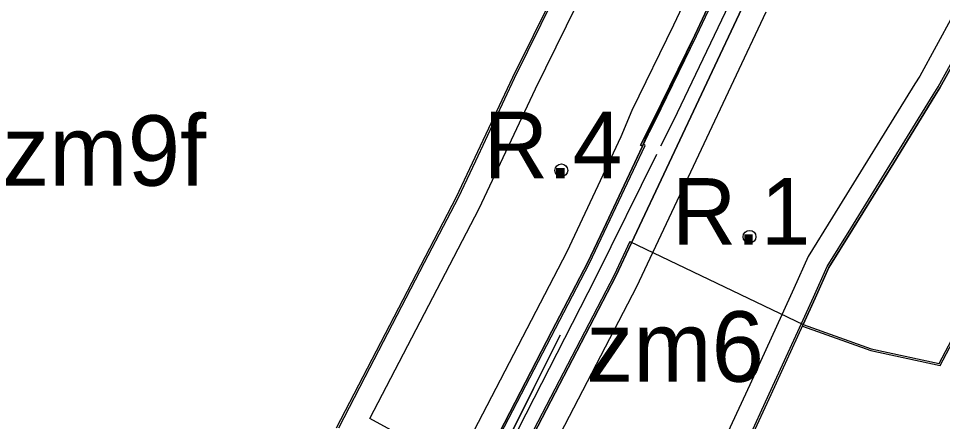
# Model space of a CAD drawing. Extents: x -555070 to -553076, y -1186731 to -1182766.
# Drawn here: x -554895.6 to -554659.4, y -1185299 to -1185196 of the extents above; entities that cross this region are included whole.
import ezdxf

# ---------------------------------------------------------------- set-up
doc = ezdxf.new("R2010")
doc.units = 0
for name, color, linetype in [('HRANICE_ZMENY_DO_KOO', 7, 'Continuous'), ('Level 10', 7, 'Continuous'), ('Level 13', 7, 'Continuous'), ('Level 4', 7, 'Continuous'), ('Level 46', 7, 'Continuous'), ('Level 52', 7, 'Continuous'), ('Level 6', 7, 'Continuous'), ('navrh_BV', 7, 'Continuous'), ('OBRYS_PLOCH', 7, 'Continuous'), ('rezerva_BV', 7, 'Continuous'), ('stav_BV', 7, 'Continuous'), ('stav_PU', 7, 'Continuous'), ('ZU_plocha_aktualizace', 7, 'Continuous')]:
    doc.layers.add(name, color=color, linetype=linetype)

msp = doc.modelspace()

# ---------------------------------------------------------------- linework, layer by layer
at = {"layer": 'HRANICE_ZMENY_DO_KOO'}
msp.add_line((-554739.32, -1185253.05), (-554694.99, -1185274.23), dxfattribs=at)
for points in [[(-554781.14, -1185319.16), (-554749.64, -1185258.53), (-554735.45, -1185228.43), (-554735.94, -1185228.17), (-554732.88, -1185222.18), (-554722.28, -1185200.47), (-554716.89, -1185189.03), (-554695.6, -1185133.26), (-554681.28, -1185085.12), (-554676.85, -1185071.58), (-554673.03, -1185055.54), (-554678.3, -1185053.24), (-554698.85, -1185044.53), (-554707.52, -1185040.87), (-554718.97, -1185084), (-554731.8, -1185124.46), (-554753.51, -1185179), (-554769.31, -1185211.12), (-554783.7, -1185241.67), (-554814.38, -1185300.72)], [(-554732.22, -1185344.93), (-554722.41, -1185327.9), (-554715.62, -1185316.12), (-554711.52, -1185309), (-554709.27, -1185304.1), (-554703.67, -1185291.93), (-554695.45, -1185274.02), (-554692.41, -1185267.29), (-554688.86, -1185259.43), (-554682.86, -1185249.71), (-554661.74, -1185215.55), (-554660.47, -1185213.5), (-554651.98, -1185198.08), (-554642.32, -1185180.53), (-554631.22, -1185160.38)], [(-554695.16, -1185274.7), (-554677.73, -1185280.92), (-554659.99, -1185284.76), (-554644.8, -1185256.02), (-554631.5, -1185230.24), (-554613.43, -1185198.97), (-554606.65, -1185185.13), (-554598.03, -1185166.4), (-554604.99, -1185165.25), (-554616.78, -1185160.64), (-554618.55, -1185165.81), (-554631.19, -1185160.33)], [(-554739.32, -1185253.05), (-554743.37, -1185261.64), (-554774.76, -1185322.08)]]:
    msp.add_lwpolyline(points, dxfattribs=at)
at = {"layer": 'Level 13'}
for p, q in [((-554753.06, -1185179.2), (-554768.86, -1185211.34)), ((-554722.73, -1185200.26), (-554717.35, -1185188.83)), ((-554709.98, -1185191.97), (-554738.91, -1185253.34)), ((-554651.54, -1185198.32), (-554660.04, -1185213.75)), ((-554660.04, -1185213.75), (-554651.54, -1185198.32)), ((-554733.33, -1185221.96), (-554722.73, -1185200.26)), ((-554768.86, -1185211.34), (-554778.8, -1185232.44)), ((-554660.04, -1185213.75), (-554661.31, -1185215.81)), ((-554661.31, -1185215.81), (-554671.87, -1185232.89)), ((-554736.6, -1185228.38), (-554733.33, -1185221.96)), ((-554746.09, -1185249.82), (-554736.11, -1185228.65)), ((-554736.11, -1185228.65), (-554736.6, -1185228.38)), ((-554778.8, -1185232.44), (-554783.25, -1185241.89)), ((-554671.87, -1185232.89), (-554682.43, -1185249.97)), ((-554682.43, -1185249.97), (-554671.87, -1185232.89)), ((-554783.25, -1185241.89), (-554791.87, -1185258.48)), ((-554750.09, -1185258.31), (-554746.09, -1185249.82)), ((-554682.43, -1185249.97), (-554688.42, -1185259.67)), ((-554688.42, -1185259.67), (-554682.43, -1185249.97)), ((-554738.91, -1185253.34), (-554742.92, -1185261.86)), ((-554759.23, -1185275.9), (-554750.09, -1185258.31)), ((-554791.87, -1185258.48), (-554807.06, -1185287.73)), ((-554688.42, -1185259.67), (-554691.95, -1185267.5)), ((-554691.95, -1185267.5), (-554688.42, -1185259.67)), ((-554742.92, -1185261.86), (-554774.32, -1185322.31)), ((-554691.95, -1185267.5), (-554694.99, -1185274.23)), ((-554694.99, -1185274.23), (-554691.95, -1185267.5)), ((-554703.22, -1185292.14), (-554694.99, -1185274.23)), ((-554694.99, -1185274.23), (-554677.59, -1185280.44)), ((-554774.2, -1185304.73), (-554759.23, -1185275.9)), ((-554677.59, -1185280.44), (-554660.25, -1185284.19)), ((-554807.06, -1185287.73), (-554813.83, -1185300.75)), ((-554708.82, -1185304.31), (-554703.22, -1185292.14))]:
    msp.add_line(p, q, dxfattribs=at)
for points in [[(-554660.25, -1185284.19), (-554645.24, -1185255.79), (-554631.94, -1185230), (-554613.87, -1185198.73), (-554607.1, -1185184.92), (-554598.76, -1185166.79), (-554605.12, -1185165.73)], [(-554671.87, -1185232.89), (-554661.31, -1185215.81), (-554660.04, -1185213.75)]]:
    msp.add_lwpolyline(points, dxfattribs=at)
at = {"layer": 'Level 4'}
for centre in [(-554756.84, -1185234.83), (-554708.72, -1185251.8)]:
    msp.add_circle(centre, 1.64, dxfattribs=at)
at = {"layer": 'Level 52'}
msp.add_lwpolyline([(-554651.54, -1185198.32), (-554660.04, -1185213.75), (-554661.31, -1185215.81), (-554671.87, -1185232.89), (-554682.43, -1185249.97), (-554688.42, -1185259.67), (-554691.95, -1185267.5), (-554694.99, -1185274.23)], dxfattribs=at)
at = {"layer": 'Level 6'}
for points in [[(-554731.38, -1185228.54), (-554728.11, -1185222.01), (-554710.22, -1185184.49), (-554693.2, -1185135.17), (-554681.62, -1185102.76), (-554672.29, -1185070.96), (-554668.89, -1185055.54)], [(-554732.53, -1185230.74), (-554748.07, -1185262.32), (-554769.87, -1185304.87)]]:
    msp.add_lwpolyline(points, dxfattribs=at)
at = {"layer": 'navrh_BV'}
for p, q in [((-554736.11, -1185228.65), (-554722.73, -1185200.26)), ((-554736.6, -1185228.38), (-554736.11, -1185228.65))]:
    msp.add_line(p, q, dxfattribs=at)
msp.add_lwpolyline([(-554722.73, -1185200.26), (-554733.33, -1185221.96), (-554736.6, -1185228.38)], dxfattribs=at)
at = {"layer": 'OBRYS_PLOCH'}
for p, q in [((-554717.35, -1185188.83), (-554722.73, -1185200.26)), ((-554717.35, -1185188.83), (-554722.73, -1185200.26)), ((-554738.91, -1185253.34), (-554709.98, -1185191.97)), ((-554738.91, -1185253.34), (-554709.98, -1185191.97)), ((-554651.54, -1185198.32), (-554660.04, -1185213.75)), ((-554736.11, -1185228.65), (-554722.73, -1185200.26)), ((-554722.73, -1185200.26), (-554736.11, -1185228.65)), ((-554722.73, -1185200.26), (-554736.11, -1185228.65)), ((-554660.04, -1185213.75), (-554661.31, -1185215.81)), ((-554661.31, -1185215.81), (-554671.87, -1185232.89)), ((-554736.11, -1185228.65), (-554746.09, -1185249.82)), ((-554736.11, -1185228.65), (-554746.09, -1185249.82)), ((-554736.6, -1185228.38), (-554736.11, -1185228.65)), ((-554671.87, -1185232.89), (-554682.43, -1185249.97)), ((-554746.09, -1185249.82), (-554750.09, -1185258.31)), ((-554746.09, -1185249.82), (-554750.09, -1185258.31)), ((-554682.43, -1185249.97), (-554688.42, -1185259.67)), ((-554742.92, -1185261.86), (-554738.91, -1185253.34)), ((-554742.92, -1185261.86), (-554738.91, -1185253.34)), ((-554750.09, -1185258.31), (-554759.23, -1185275.9)), ((-554750.09, -1185258.31), (-554759.23, -1185275.9)), ((-554688.42, -1185259.67), (-554691.95, -1185267.5)), ((-554774.32, -1185322.31), (-554742.92, -1185261.86)), ((-554774.32, -1185322.31), (-554742.92, -1185261.86)), ((-554691.95, -1185267.5), (-554694.99, -1185274.23)), ((-554694.99, -1185274.23), (-554677.59, -1185280.44)), ((-554759.23, -1185275.9), (-554774.2, -1185304.73)), ((-554759.23, -1185275.9), (-554774.2, -1185304.73)), ((-554677.59, -1185280.44), (-554660.25, -1185284.19))]:
    msp.add_line(p, q, dxfattribs=at)
for points in [[(-554660.25, -1185284.19), (-554645.24, -1185255.79), (-554631.94, -1185230), (-554613.87, -1185198.73), (-554607.1, -1185184.92), (-554598.76, -1185166.79), (-554605.12, -1185165.73)], [(-554722.73, -1185200.26), (-554733.33, -1185221.96), (-554736.6, -1185228.38)]]:
    msp.add_lwpolyline(points, dxfattribs=at)
at = {"layer": 'rezerva_BV'}
for p, q in [((-554753.06, -1185179.2), (-554768.86, -1185211.34)), ((-554753.06, -1185179.2), (-554768.86, -1185211.34)), ((-554722.73, -1185200.26), (-554717.35, -1185188.83)), ((-554722.73, -1185200.26), (-554717.35, -1185188.83)), ((-554709.98, -1185191.97), (-554738.91, -1185253.34)), ((-554709.98, -1185191.97), (-554738.91, -1185253.34)), ((-554660.04, -1185213.75), (-554651.54, -1185198.32)), ((-554660.04, -1185213.75), (-554651.54, -1185198.32)), ((-554733.33, -1185221.96), (-554722.73, -1185200.26)), ((-554768.86, -1185211.34), (-554778.8, -1185232.44)), ((-554768.86, -1185211.34), (-554778.8, -1185232.44)), ((-554661.31, -1185215.81), (-554660.04, -1185213.75)), ((-554661.31, -1185215.81), (-554660.04, -1185213.75)), ((-554671.87, -1185232.89), (-554661.31, -1185215.81)), ((-554671.87, -1185232.89), (-554661.31, -1185215.81)), ((-554736.11, -1185228.65), (-554733.33, -1185221.96)), ((-554746.09, -1185249.82), (-554736.11, -1185228.65)), ((-554746.09, -1185249.82), (-554736.11, -1185228.65)), ((-554736.11, -1185228.65), (-554736.6, -1185228.38)), ((-554778.8, -1185232.44), (-554783.25, -1185241.89)), ((-554778.8, -1185232.44), (-554783.25, -1185241.89)), ((-554682.43, -1185249.97), (-554671.87, -1185232.89)), ((-554682.43, -1185249.97), (-554671.87, -1185232.89)), ((-554783.25, -1185241.89), (-554791.87, -1185258.48)), ((-554783.25, -1185241.89), (-554791.87, -1185258.48)), ((-554687.53, -1185246.82), (-554693.73, -1185256.85)), ((-554750.09, -1185258.31), (-554746.09, -1185249.82)), ((-554688.42, -1185259.67), (-554682.43, -1185249.97)), ((-554688.42, -1185259.67), (-554682.43, -1185249.97)), ((-554738.91, -1185253.34), (-554742.92, -1185261.86)), ((-554738.91, -1185253.34), (-554742.92, -1185261.86)), ((-554759.23, -1185275.9), (-554750.09, -1185258.31)), ((-554693.73, -1185256.85), (-554697.42, -1185265.03)), ((-554791.87, -1185258.48), (-554807.06, -1185287.73)), ((-554791.87, -1185258.48), (-554807.06, -1185287.73)), ((-554691.95, -1185267.5), (-554688.42, -1185259.67)), ((-554691.95, -1185267.5), (-554688.42, -1185259.67)), ((-554742.92, -1185261.86), (-554774.32, -1185322.31)), ((-554742.92, -1185261.86), (-554774.32, -1185322.31)), ((-554697.42, -1185265.03), (-554700.45, -1185271.74)), ((-554694.99, -1185274.23), (-554691.95, -1185267.5)), ((-554694.99, -1185274.23), (-554691.95, -1185267.5)), ((-554700.45, -1185271.74), (-554708.67, -1185289.63)), ((-554703.22, -1185292.14), (-554694.99, -1185274.23)), ((-554703.22, -1185292.14), (-554694.99, -1185274.23)), ((-554774.2, -1185304.73), (-554759.23, -1185275.9)), ((-554774.2, -1185304.73), (-554759.23, -1185275.9)), ((-554807.06, -1185287.73), (-554813.83, -1185300.75)), ((-554807.06, -1185287.73), (-554813.83, -1185300.75)), ((-554708.67, -1185289.63), (-554714.27, -1185301.8)), ((-554708.82, -1185304.31), (-554703.22, -1185292.14)), ((-554708.82, -1185304.31), (-554703.22, -1185292.14))]:
    msp.add_line(p, q, dxfattribs=at)
for points in [[(-554755.47, -1185255.65), (-554783.85, -1185310.28), (-554805.8, -1185298.3), (-554777.88, -1185244.55), (-554763.45, -1185213.94), (-554747.57, -1185181.64), (-554725.82, -1185127.02), (-554704.58, -1185138.55), (-554722.87, -1185186.48), (-554728.14, -1185197.66), (-554738.8, -1185219.49), (-554741.6, -1185226.21), (-554755.47, -1185255.65)], [(-554655.3, -1185156.98), (-554639.41, -1185163.85), (-554647.14, -1185177.88), (-554656.8, -1185195.43), (-554665.22, -1185210.73), (-554666.42, -1185212.66), (-554687.53, -1185246.82)], [(-554766.29, -1185319.86), (-554737.54, -1185264.52), (-554704.46, -1185194.32)], [(-554736.6, -1185228.38), (-554733.33, -1185221.96), (-554722.73, -1185200.26)], [(-554759.23, -1185275.9), (-554750.09, -1185258.31), (-554746.09, -1185249.82)]]:
    msp.add_lwpolyline(points, dxfattribs=at)
at = {"layer": 'stav_BV'}
for p, q in [((-554651.54, -1185198.32), (-554660.04, -1185213.75)), ((-554660.04, -1185213.75), (-554661.31, -1185215.81)), ((-554661.31, -1185215.81), (-554671.87, -1185232.89)), ((-554671.87, -1185232.89), (-554682.43, -1185249.97)), ((-554682.43, -1185249.97), (-554688.42, -1185259.67)), ((-554688.42, -1185259.67), (-554691.95, -1185267.5)), ((-554691.95, -1185267.5), (-554694.99, -1185274.23)), ((-554694.99, -1185274.23), (-554677.59, -1185280.44)), ((-554677.59, -1185280.44), (-554660.25, -1185284.19))]:
    msp.add_line(p, q, dxfattribs=at)
msp.add_lwpolyline([(-554660.25, -1185284.19), (-554645.24, -1185255.79), (-554631.94, -1185230), (-554613.87, -1185198.73), (-554607.1, -1185184.92), (-554598.76, -1185166.79), (-554605.12, -1185165.73)], dxfattribs=at)
at = {"layer": 'stav_PU'}
for p, q in [((-554717.35, -1185188.83), (-554722.73, -1185200.26)), ((-554717.35, -1185188.83), (-554722.73, -1185200.26)), ((-554738.91, -1185253.34), (-554709.98, -1185191.97)), ((-554722.73, -1185200.26), (-554736.11, -1185228.65)), ((-554722.73, -1185200.26), (-554736.11, -1185228.65)), ((-554736.11, -1185228.65), (-554746.09, -1185249.82)), ((-554736.11, -1185228.65), (-554746.09, -1185249.82)), ((-554746.09, -1185249.82), (-554750.09, -1185258.31)), ((-554746.09, -1185249.82), (-554750.09, -1185258.31)), ((-554742.92, -1185261.86), (-554738.91, -1185253.34)), ((-554742.92, -1185261.86), (-554738.91, -1185253.34)), ((-554750.09, -1185258.31), (-554759.23, -1185275.9)), ((-554750.09, -1185258.31), (-554759.23, -1185275.9)), ((-554774.32, -1185322.31), (-554742.92, -1185261.86)), ((-554774.32, -1185322.31), (-554742.92, -1185261.86)), ((-554759.23, -1185275.9), (-554774.2, -1185304.73)), ((-554759.23, -1185275.9), (-554774.2, -1185304.73)), ((-554771.69, -1185306.03), (-554757.18, -1185276.99)), ((-554757.18, -1185276.99), (-554764, -1185290.64)), ((-554764, -1185290.64), (-554771.69, -1185306.03))]:
    msp.add_line(p, q, dxfattribs=at)
msp.add_lwpolyline([(-554738.91, -1185253.34), (-554709.98, -1185191.97), (-554688.49, -1185135.67)], dxfattribs=at)
at = {"layer": 'ZU_plocha_aktualizace'}
for p, q in [((-554651.54, -1185198.32), (-554660.04, -1185213.75)), ((-554660.04, -1185213.75), (-554661.31, -1185215.81)), ((-554661.31, -1185215.81), (-554671.87, -1185232.89)), ((-554671.87, -1185232.89), (-554682.43, -1185249.97)), ((-554682.43, -1185249.97), (-554688.42, -1185259.67)), ((-554688.42, -1185259.67), (-554691.95, -1185267.5)), ((-554691.95, -1185267.5), (-554694.99, -1185274.23)), ((-554694.99, -1185274.23), (-554677.59, -1185280.44)), ((-554677.59, -1185280.44), (-554660.25, -1185284.19))]:
    msp.add_line(p, q, dxfattribs=at)
msp.add_lwpolyline([(-554660.25, -1185284.19), (-554645.24, -1185255.79), (-554631.94, -1185230), (-554613.87, -1185198.73), (-554607.1, -1185184.92), (-554598.76, -1185166.79), (-554605.12, -1185165.73)], dxfattribs=at)

# ---------------------------------------------------------------- texts
at = {"layer": 'Level 10'}
for s, p in [('zm9f', (-554899.8, -1185238.75)), ('zm6', (-554750.5, -1185288.86))]:
    msp.add_text(s, height=18, dxfattribs=at).set_placement(p)
at = {"layer": 'Level 46'}
for s, p in [('R.4', (-554776.66, -1185236.84)), ('R.1', (-554728.55, -1185253.82))]:
    msp.add_text(s, height=17, dxfattribs=at).set_placement(p)

doc.saveas('drawing.dxf')
